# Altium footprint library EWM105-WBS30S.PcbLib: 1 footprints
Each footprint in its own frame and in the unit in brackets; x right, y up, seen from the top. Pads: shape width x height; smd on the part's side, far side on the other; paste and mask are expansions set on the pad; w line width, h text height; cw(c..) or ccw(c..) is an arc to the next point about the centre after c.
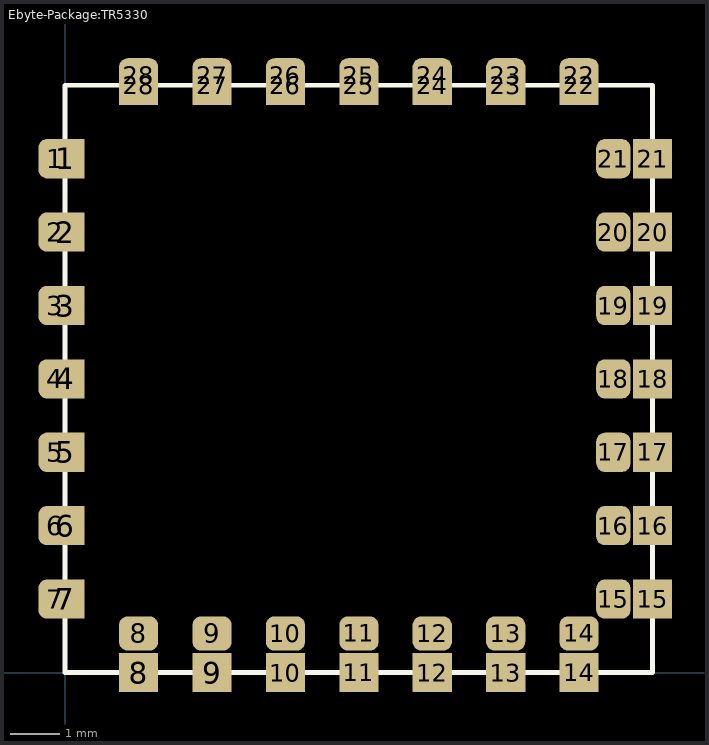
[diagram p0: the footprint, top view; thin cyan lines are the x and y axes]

## Ebyte-Package:TR5330 [mil]
pads (56):
  rrect50% 27.6x31.5 smd paste+0 mask+0: 1(-7.8,413.4) 2(-7.8,354.4) 3(-7.8,295.3) 4(-7.8,236.3) 5(-7.8,177.2) 6(-7.8,118.2) 7(-7.8,59.1) 15(441,59.1) 16(441,118.2) 17(441,177.2) 18(441,236.3) 19(441,295.3) 20(441,354.4) 21(441,413.4)
  rect 31.5x31.5 smd paste+0 mask+0: 1(0,413.4) 2(0,354.4) 3(0,295.3) 4(0,236.3) 5(0,177.2) 6(0,118.2) 7(0,59.1) 8(59.1,0) 9(118.2,0) 10(177.2,0) 11(236.3,0) 12(295.3,0) 13(354.4,0) 14(413.4,0) 15(472.5,59.1) 16(472.5,118.2) 17(472.5,177.2) 18(472.5,236.3) 19(472.5,295.3) 20(472.5,354.4) 21(472.5,413.4) 22(413.4,472.5) 23(354.4,472.5) 24(295.3,472.5) 25(236.3,472.5) 26(177.2,472.5) 27(118.2,472.5) 28(59.1,472.5)
  rrect50% 31.5x27.6 smd paste+0 mask+0: 8(59.1,31.5) 9(118.2,31.5) 10(177.2,31.5) 11(236.3,31.5) 12(295.3,31.5) 13(354.4,31.5) 14(413.4,31.5) 22(413.4,480.4) 23(354.4,480.4) 24(295.3,480.4) 25(236.3,480.4) 26(177.2,480.4) 27(118.2,480.4) 28(59.1,480.4)
Top Overlay:
  lines w3.9: 0,0 472.5,0 472.5,472.5 0,472.5 0,0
